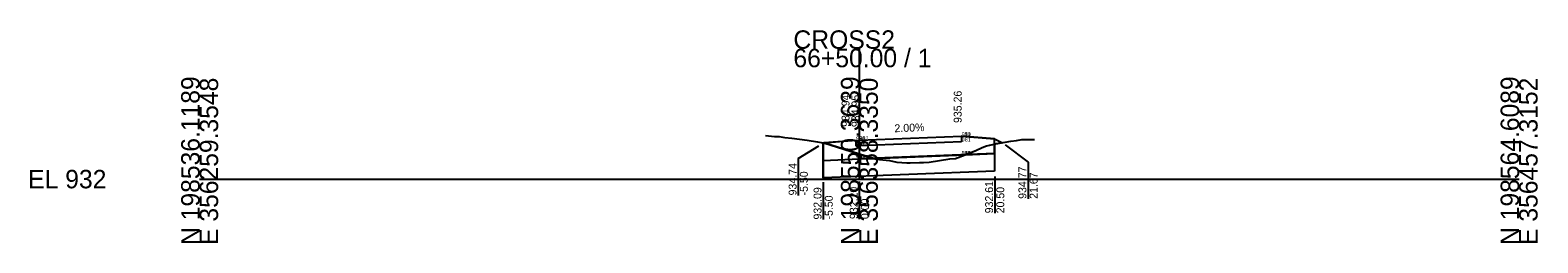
# Model space of a CAD drawing. Extents: x -26 to 203, y -10 to 14021.
# Drawn here: x -25.7 to 202.8, y 7490.3 to 7522.6 of the extents above; entities that cross this region are included whole.
import ezdxf

# ---------------------------------------------------------------- set-up
doc = ezdxf.new("R2010")
doc.units = 0
for name, color, linetype in [('Default', 7, 'Continuous'), ('P_E_XS_Ground', 7, 'Continuous'), ('P_XS', 7, 'Continuous'), ('P_XS_Bold', 7, 'Continuous'), ('P_XS_EAR_CommonGrnd', 7, 'Continuous'), ('P_XS_Lane', 7, 'Continuous'), ('P_XS_Rock', 7, 'Continuous')]:
    doc.layers.add(name, color=color, linetype=linetype)

msp = doc.modelspace()

# ---------------------------------------------------------------- linework, layer by layer
at = {"layer": 'Default'}
for p, q in [((100, 7500), (100, 7519.79)), ((0, 7500), (100, 7500)), ((100, 7500), (200, 7500))]:
    msp.add_line(p, q, dxfattribs=at)
at = {"layer": 'P_E_XS_Ground'}
for p, q in [((85.75, 7506.6), (87.12, 7506.49)), ((87.12, 7506.49), (87.83, 7506.48)), ((87.83, 7506.48), (88.38, 7506.38)), ((88.38, 7506.38), (88.68, 7506.32)), ((88.68, 7506.32), (89.76, 7506.2)), ((89.76, 7506.2), (92.08, 7505.93)), ((92.08, 7505.93), (93.63, 7505.65)), ((93.63, 7505.65), (94.74, 7505.48)), ((94.74, 7505.48), (97.66, 7504.54)), ((118.59, 7504.81), (119.28, 7505.04)), ((119.28, 7505.04), (120.67, 7505.37)), ((120.67, 7505.37), (122.98, 7505.74)), ((122.98, 7505.74), (123.82, 7505.88)), ((123.82, 7505.88), (124.61, 7506)), ((124.61, 7506), (125.19, 7506.02)), ((125.19, 7506.02), (126.52, 7506.03)), ((97.66, 7504.54), (100, 7503.79)), ((100, 7503.79), (102.52, 7503.04)), ((102.52, 7503.04), (104.58, 7502.83)), ((104.58, 7502.83), (105.67, 7502.56)), ((110.59, 7502.59), (113.71, 7503.08)), ((113.71, 7503.08), (114.58, 7503.15)), ((114.58, 7503.15), (117.67, 7504.34)), ((117.67, 7504.34), (118.59, 7504.81)), ((105.67, 7502.56), (107.21, 7502.48)), ((107.21, 7502.48), (107.7, 7502.47)), ((107.7, 7502.47), (109.13, 7502.5)), ((109.13, 7502.5), (109.73, 7502.53)), ((109.73, 7502.53), (110.59, 7502.59))]:
    msp.add_line(p, q, dxfattribs=at)
at = {"layer": 'P_XS'}
for p, q in [((94.5, 7502.84), (94.5, 7505.48)), ((99.5, 7505.88), (99.5, 7505.04)), ((99.5, 7505.04), (100, 7505.06)), ((115.5, 7505.68), (100, 7505.06)), ((115.5, 7506.52), (115.5, 7505.68)), ((120.5, 7503.88), (120.5, 7506.12)), ((94.5, 7502.84), (100, 7503.06)), ((94.5, 7502.84), (94.5, 7500.17)), ((120.5, 7503.88), (100, 7503.06)), ((120.5, 7503.88), (120.5, 7501.21)), ((120.5, 7501.21), (94.5, 7500.17))]:
    msp.add_line(p, q, dxfattribs=at)
at = {"layer": 'P_XS_EAR_CommonGrnd'}
for points in [[(94.67, 7505.49), (94.5, 7505.48), (94.5, 7502.84), (100, 7503.06), (102.15, 7503.15), (100, 7503.79), (97.66, 7504.54), (94.74, 7505.48)], [(115.5, 7505.68), (100, 7505.06), (99.5, 7505.04), (99.5, 7505.88), (94.67, 7505.49), (94.74, 7505.48), (97.66, 7504.54), (100, 7503.79), (102.15, 7503.15), (116.01, 7503.7), (117.67, 7504.34), (118.59, 7504.81), (119.28, 7505.04), (120.5, 7505.33), (120.5, 7506.12), (115.5, 7506.52)], [(115.5, 7505.68), (100, 7505.06), (99.5, 7505.04), (99.5, 7505.88), (100, 7505.9), (115.5, 7506.52)], [(118.59, 7504.81), (119.28, 7505.04), (120.5, 7505.33), (120.5, 7503.88), (116.01, 7503.7), (117.67, 7504.34)], [(120.5, 7505.33), (120.5, 7506.12), (121.67, 7505.53), (120.67, 7505.37)], [(120.5, 7501.21), (94.5, 7500.17), (94.5, 7502.84), (100, 7503.06), (102.15, 7503.15), (102.52, 7503.04), (104.58, 7502.83), (105.67, 7502.56), (107.21, 7502.48), (107.7, 7502.47), (109.13, 7502.5), (109.73, 7502.53), (110.59, 7502.59), (113.71, 7503.08), (114.58, 7503.15), (116.01, 7503.7), (120.5, 7503.88)], [(114.58, 7503.15), (116.01, 7503.7), (102.15, 7503.15), (102.52, 7503.04), (104.58, 7502.83), (105.67, 7502.56), (107.21, 7502.48), (107.7, 7502.47), (109.13, 7502.5), (109.73, 7502.53), (110.59, 7502.59), (113.71, 7503.08)]]:
    msp.add_lwpolyline(points, close=True, dxfattribs=at)
at = {"layer": 'P_XS_Lane'}
for p, q in [((99.5, 7505.88), (94.5, 7505.48)), ((99.5, 7505.88), (100, 7505.9)), ((100, 7505.9), (115.5, 7506.52)), ((115.5, 7506.52), (120.5, 7506.12)), ((120.5, 7506.12), (121.67, 7505.53))]:
    msp.add_line(p, q, dxfattribs=at)
at = {"layer": 'P_XS_Rock'}
for p, q in [((90.73, 7503.12), (93.85, 7505.07)), ((122.12, 7505.19), (125.56, 7502.59)), ((90.73, 7503.12), (90.73, 7497.52)), ((125.56, 7502.59), (125.56, 7497)), ((94.51, 7499.55), (94.51, 7493.86)), ((99.99, 7499.63), (99.99, 7493.93)), ((120.51, 7500.4), (120.51, 7494.8))]:
    msp.add_line(p, q, dxfattribs=at)

# ---------------------------------------------------------------- texts
at = {"layer": 'Default'}
for s, p in [('CROSS2', (90, 7519.79)), ('66+50.00 / 1', (90, 7516.99)), ('EL 932', (-26, 7498.6))]:
    msp.add_text(s, height=2.8, dxfattribs=at).set_placement(p)
for s, p in [('N 198536.1189', (0, 7490)), ('E 356259.3548', (2.8, 7490)), ('N 198550.3639', (100, 7490)), ('E 356358.3350', (102.8, 7490)), ('N 198564.6089', (200, 7490)), ('E 356457.3152', (202.8, 7490))]:
    msp.add_text(s, height=2.8, rotation=90, dxfattribs=at).set_placement(p)
at = {"layer": 'P_XS_Bold'}
for s, p in [('951', (99.5, 7505.88)), ('9', (99.5, 7505.88)), ('900', (99.5, 7505.88)), ('961', (99.5, 7505.04)), ('952', (100, 7505.9)), ('952', (100, 7505.9)), ('962', (100, 7505.06)), ('962', (100, 7505.06)), ('951', (115.5, 7506.52)), ('9', (115.5, 7506.52)), ('900', (115.5, 7506.52)), ('910', (115.5, 7506.52)), ('961', (115.5, 7505.68)), ('971', (99.5, 7503.04)), ('998', (99.5, 7503.04)), ('972', (100, 7503.06)), ('972', (100, 7503.06)), ('540', (115.5, 7503.68)), ('971', (115.5, 7503.68)), ('998', (115.5, 7503.68))]:
    msp.add_text(s, height=0.6, dxfattribs=at).set_placement(p)
at = {"layer": 'P_XS_Rock'}
for s, rotation, p in [('934.94', 90, (98.5, 7507.94)), ('934.95', 90, (100, 7507.9)), ('934.95', 90, (100, 7507.9)), ('934.95', 90, (100, 7507.9)), ('934.95', 90, (100, 7507.9)), ('935.26', 90, (115.5, 7508.52)), ('2.00%', 2.2906, (105.34, 7507.11)), ('934.74', 90, (90.48, 7497.52)), ('-5.50', 90, (92.18, 7497.52)), ('934.77', 90, (125.31, 7497)), ('21.67', 90, (127.01, 7497)), ('932.09', 90, (94.26, 7493.86)), ('932.20', 90, (99.74, 7493.93)), ('932.61', 90, (120.26, 7494.8)), ('20.50', 90, (121.96, 7494.8)), ('-5.50', 90, (95.96, 7493.86)), ('0.00', 90, (101.44, 7493.93))]:
    msp.add_text(s, height=1.2, rotation=rotation, dxfattribs=at).set_placement(p)

doc.saveas('drawing.dxf')
